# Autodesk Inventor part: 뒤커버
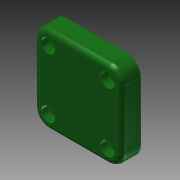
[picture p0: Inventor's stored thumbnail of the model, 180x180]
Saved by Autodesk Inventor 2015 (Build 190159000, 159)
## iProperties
Created: 2018-07
Part Number: 뒤커버
Material: 알루미늄 6061
Document SubType Name: Modeling
Designer: mduedu
Density: 1 g/cm^3
Appearance: 매끄러움 - 짙은 산림 녹색
Author: mduedu
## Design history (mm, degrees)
sketch "스케치1"
  geometry: C1 r 16 at (0, 0); 1 further point
  constraints: 1 centre point, 1 coincident
  dimensions: "d0" = 32 diameter of C1
extrude "돌출1" new body sketch "스케치1" distance "d1" = 3; taper "d2" = 0 deg
sketch "스케치2"
  geometry: L1 (-25, -25)-(25, -25); L2 (25, -25)-(25, 25); L3 (25, 25)-(-25, 25); L4 (-25, 25)-(-25, -25); L5 (-25, -25)-(25, 25); L6 (25, -25)-(-25, 25); 1 further point
  constraints: 12 end point, 2 midpoint, 2 parallel, 1 horizontal, 1 perpendicular
  dimensions: "d3" = 50 distance of L3.end L2.end; "d4" = 50 distance of L2.end L1.end
extrude "돌출2" join sketch "스케치2" distance "d5" = 11; taper "d6" = 0 deg
hole "구멍1" diameter "d9" = 25; stored, may be unused: countersink angle "d13" = 90 deg, drill point angle "d15" = 0 deg; dims "d7" = 10, "d8" = 10, "d10" = 6, "d11" = 4, "d12" = 2, "d14" = 3
fillet "모깎기2" dims "d26" = 3
fillet "모깎기3" dims "d27" = 8
sketch "스케치5"
  geometry: L1 (25, -17)-(25, 17) reference; L2 (17, 25)-(-17, 25) reference; L3 (-25, 17)-(-25, -17) reference; L4 (-17, -25)-(17, -25) reference; A1 r 8 centre (17, -17) between (17, -25) and (25, -17) reference; A2 r 8 centre (17, 17) between (25, 17) and (17, 25) reference; A3 r 8 centre (-17, 17) between (-17, 25) and (-25, 17) reference; A4 r 8 centre (-17, -17) between (-25, -17) and (-17, -25) reference; 5 further points
  constraints: 4 coincident
hole "구멍2" sketch "스케치5" at (-17, 17), (17, 17), (17, -17), (-17, -17) diameter "d28" = 4.5; stored, may be unused: countersink angle "d32" = 90 deg, drill point angle "d34" = 0 deg; dims "d29" = 6, "d30" = 8, "d31" = 4.6, "d33" = 3
fillet "모깎기4" dims "d35" = 3
chamfer "모따기2" distance "d36" = 1; stored, may be unused: second distance "d37" = 2, angle "d38" = 45 deg
node "솔리드1"
node "투영된 루프1"
